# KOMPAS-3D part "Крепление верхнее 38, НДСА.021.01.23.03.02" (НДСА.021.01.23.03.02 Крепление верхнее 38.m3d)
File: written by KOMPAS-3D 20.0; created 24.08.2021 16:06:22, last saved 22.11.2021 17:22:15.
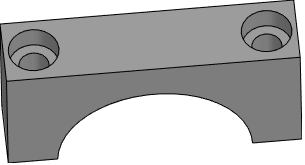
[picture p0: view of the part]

Document properties: Полное имя файла: C:\Users\s.pischagina\Desktop\PLM\НДСА.021.01.23.03.02 Крепление верхнее 38.m3d

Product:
- Part/product: Крепление верхнее 38  | designation НДСА.021.01.23.03.02
    Материал: АМг6  ГОСТ 4784-2019 (density 2640 kg/m3)
    Масса: 0.0317194
    additional columns: <item xmlns="http://appius.ru/pdm" xmlns:xs="http://www.w3.org/2001/XMLSchema" x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; <item xmlns="http://appius.ru/pdm" xmlns:xs="http://www.w3.org/2001/XMLSchema" x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; <item xmlns="http://appius.ru/pdm" xmlns:xs="http://www.w3.org/2001/XMLSchema" x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
    source file: НДСА.021.01.23.03.02 Крепление верхнее 38.cdw

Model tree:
1. Эскиз:1
2. Элемент выдавливания:1
     Расстояние 1 = 80
3. Эскиз:2  (with: Элемент выдавливания:1)
4. Элемент выдавливания:2
5. Эскиз:3  (with: Элемент выдавливания:1, Элемент выдавливания:2)
6. Элемент выдавливания:3
7. Отверстие:1  (with: Элемент выдавливания:1)
     Глубина выреза = 80; Диаметр отверстия = 6; Угол конуса дна = 118; Расстояние 1 = 7; Расстояние 2 = 59; Диаметр цековки = 10; Глубина цековки = 5
8. M5  (with: Элемент выдавливания:3)  (labels: M5; cil0_24705-2004 coarse)
     Длина резьбы = 30; Шаг резьбы = 0.8; Номинальный диаметр резьбы = 5
9. Отверстие:2  (with: Элемент выдавливания:1, M5, Элемент выдавливания:3)  (labels: M5; cil0_24705-2004 coarse)
     Глубина выреза = 80; Диаметр отверстия = 6; Угол конуса дна = 118; Расстояние 1 = 7; Расстояние 2 = 13; Диаметр цековки = 10; Глубина цековки = 5; Длина резьбы = 30; Шаг резьбы = 0.8; Номинальный диаметр резьбы = 5
10. Эскиз:4  (with: Элемент выдавливания:3)
11. Элемент выдавливания:5
     Расстояние 2 = 49
12. Элемент выдавливания:6  (with: Элемент выдавливания:1)
     Расстояние 2 = 7
13. Элемент выдавливания:7  (with: Элемент выдавливания:1)  (labels: АМг6  ГОСТ 4784-2019)
     Расстояние 2 = 7

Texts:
  НДСА.021.01.23.03.02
